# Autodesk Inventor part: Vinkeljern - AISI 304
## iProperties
Company: Cad-Q A/S
Author: Administrator
Shininess: 25.0
PropertySet Name: _Private Model Information
Created: 2001-02
Part Number: Vinkeljern - AISI 304
Material: Stainless Steel, AISI 304
Document SubType Name: Modeling
Designer: Administrator
Control State: 0
Master: False
Checked Out: False
PropertySet Name: Design Tracking Control
Density: 8.03
Volumn: 1.3093138785576415
Area: 11.68986722862693
PropertySet Name: Model Information
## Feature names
1. Extrusion1
2. Fillet1
